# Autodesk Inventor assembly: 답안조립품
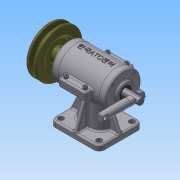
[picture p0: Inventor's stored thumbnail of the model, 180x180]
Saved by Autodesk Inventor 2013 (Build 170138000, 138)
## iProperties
Created: 2015-05
Part Number: 답안조립품
Document SubType Name: Assembly
Designer: Administrator
Author: Administrator
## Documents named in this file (18)
- C:\Users\Administrator\Desktop\350508V1043\답안조립품.iam
- C:\Users\Administrator\Desktop\350508V1043\본체.ipt
- C:\Users\Administrator\Desktop\350508V1043\M3x0.5x8.ipt
- C:\Users\Administrator\Desktop\350508V1043\M4x0.5x14.ipt
- C:\Users\Administrator\Desktop\350508V1043\V-벨트풀리.ipt
- C:\Users\Administrator\Desktop\350508V1043\가변 스프링.ipt
- C:\Users\Administrator\Desktop\350508V1043\너트 M8.ipt
- C:\Users\Administrator\Desktop\350508V1043\뒤커버.ipt
- C:\Users\Administrator\Desktop\350508V1043\링크.ipt
- C:\Users\Administrator\Desktop\350508V1043\멈춤나사.ipt
- C:\Users\Administrator\Desktop\350508V1043\베어링 6201.ipt
- C:\Users\Administrator\Desktop\350508V1043\베어링 6202.ipt
- C:\Users\Administrator\Desktop\350508V1043\본체 커버.ipt
- C:\Users\Administrator\Desktop\350508V1043\슬라이드.ipt
- C:\Users\Administrator\Desktop\350508V1043\앞커버.ipt
- C:\Users\Administrator\Desktop\350508V1043\오일실.ipt
- C:\Users\Administrator\Desktop\350508V1043\키4x4.ipt
- C:\Users\Administrator\Desktop\350508V1043\편심축.ipt
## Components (15 placed, 5 different names)
1. M4x0.5x14:1
2. V-벨트풀리:1 — 플러쉬:1
3. 가변 스프링:1
4. KS B 1012 C - 미터 C M8:1
5. M4x0.5x14:2
6. M4x0.5x14:3
7. M4x0.5x14:4
8. M3x0.5x8:2
9. M3x0.5x8:3
10. M3x0.5x8:4
11. M3x0.5x8:5
12. M3x0.5x8:1
13. M3x0.5x8:6
14. M3x0.5x8:7
15. M3x0.5x8:8
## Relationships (1: Flush 1)
- 플러쉬:1 [Flush]: V-벨트풀리:1
